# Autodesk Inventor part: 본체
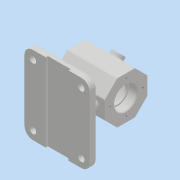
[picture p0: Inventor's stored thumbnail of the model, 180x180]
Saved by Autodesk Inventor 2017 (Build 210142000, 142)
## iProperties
Part Number: 본체
Material: 일반
Document SubType Name: Modeling
Designer: MRC
Density: 1 g/cm^3
Appearance: 기본값
Author: MRC
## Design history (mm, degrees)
sketch "스케치1"
  geometry: L1 (-35, 40)-(35, 40); L2 (35, 40)-(35, 16); L3 (35, 16)-(23, 16); L4 (23, 16)-(23, 14); L5 (23, 14)-(20, 14); L6 (20, 14)-(20, 25); L7 (20, 25)-(-20, 25); L8 (-20, 25)-(-20, 14); L9 (-20, 14)-(-23, 14); L10 (-23, 14)-(-23, 16); L11 (-23, 16)-(-35, 16); L12 (-35, 16)-(-35, 40); L13 (-35, 0)-(35, 0); 3 further points
  constraints: 26 end point, 10 perpendicular, 5 point on line, 3 midpoint, 2 vertical alignment, 1 horizontal
  dimensions: "d0" = 35 distance from line of point (0, 0) L12; "d1" = 35 distance from line of point (0, 0) L2; "d2" = 12 distance of L10.end L11.end; "d4" = 40 distance of L6.end L7.end; "d5" = 12 distance of L2.end L3.end; "d6" = 32 diameter of L11 L13; "d7" = 28 diameter of L9 L13; "d8" = 80 diameter of L1 L13; "d9" = 50 diameter of L7 L13
revolve "회전1" sketch "스케치1" stored, may be unused: angle "d10" = 90 deg
sketch "스케치2"
  geometry: L1 (30, 12.426)-(30, -12.426); L2 (30, -12.426)-(12.426, -30); L3 (12.426, -30)-(-12.426, -30); L4 (-12.426, -30)-(-30, -12.426); L5 (-30, -12.426)-(-30, 12.426); L6 (-30, 12.426)-(-12.426, 30); L7 (-12.426, 30)-(12.426, 30); L8 (12.426, 30)-(30, 12.426); 2 further points
  constraints: 16 end point, 1 coincident, 1 horizontal, 17 other
  dimensions: "d62" = 60 distance between parallel lines of L3 L7
extrude "돌출1" sketch "스케치2" stored distance "d12" = 0; taper "d13" = 0 deg
sketch "스케치4"
  geometry: L1 (-52, -55)-(-62, -55); L2 (-62, -55)-(-62, 55); L3 (-62, 55)-(-52, 55); L4 (-52, 55)-(-52, -55); 2 further points
  constraints: 8 end point, 2 parallel, 1 horizontal, 1 horizontal alignment, 1 midpoint, 1 perpendicular
  dimensions: "d26" = 62 distance from line of point (0, 0) L2; "d27" = 10 distance of L2.end L3.end; "d28" = 110 distance of L1.end L2.end
extrude "돌출2" join sketch "스케치4" stored distance "d29" = 92; taper "d30" = 0 deg
sketch "스케치5"
  geometry: L1 (26, 55)-(66, 55); L2 (26, 61)-(66, 61); L3 (66, 49)-(26, 49); A1 r 6 centre (26, 55) between (26, 61) and (26, 49); A2 r 6 centre (66, 55) between (66, 49) and (66, 61); 2 further points
  constraints: 8 end point, 4 point on circle, 4 tangent, 2 centre point, 1 coincident, 1 horizontal, 1 midpoint, 1 parallel
  dimensions: "d32" = 12 distance between parallel lines of L3 L2; "d97" = 40 distance of L1.start L1.end
extrude "돌출3" join sketch "스케치5" stored distance "d33" = 92; taper "d34" = 0 deg
fillet "모깎기1" dims "d35" = 12
sketch "스케치6"
  geometry: L1 (80, -98)-(80, -12) reference; L2 (68, -110)-(0, -110) reference; L3 (-12, -12)-(-12, -98) reference; L4 (68, 0)-(0, 0) reference; A1 r 12 centre (68, -12) between (80, -12) and (68, 0) reference; A2 r 12 centre (68, -98) between (68, -110) and (80, -98) reference; A3 r 12 centre (0, -98) between (-12, -98) and (0, -110) reference; A4 r 12 centre (0, -12) between (0, 0) and (-12, -12) reference; 5 further points
  constraints: 4 coincident
hole "구멍2" sketch "스케치6" at (0, -12), (68, -12), (68, -98), (0, -98) diameter "d36" = 9; stored, may be unused: countersink angle "d40" = 90 deg, drill point angle "d42" = 118 deg; dims "d37" = 8, "d38" = 4, "d39" = 2, "d41" = 10
sketch "스케치7"
  geometry: L1 (68, -10)-(0, -10) reference; L2 (18, -7)-(50, -7); L3 (50, -7)-(50, -10); L4 (50, -10)-(18, -10); L5 (18, -10)-(18, -7); L6 (18, -7)-(50, -10); L7 (50, -7)-(18, -10); 3 further points
  constraints: 12 end point, 3 midpoint, 2 parallel, 1 horizontal, 1 perpendicular, 1 point on line, 1 vertical alignment
  dimensions: "d43" = 32 distance of L2.start L2.end; "d44" = 3 distance of L2.end L3.end
extrude "돌출4" cut sketch "스케치7" stored distance "d45" = 92; taper "d46" = 0 deg
sketch "스케치11"
  geometry: 2 further points
  constraints: 1 vertical alignment
  dimensions: "d63" = 23 distance of point (30, 12.426) point (30, 35.426)
hole "구멍4" sketch "스케치11" at (30, 35.426) diameter "d64" = 3.242; stored, may be unused: countersink angle "d68" = 90 deg, drill point angle "d70" = 118 deg; dims "d65" = 8, "d66" = 4, "d67" = 2, "d69" = 10
sketch "스케치12"
  geometry: C1 r 8 at (35, -12.426); 1 further point
  constraints: 1 centre point, 1 coincident
  dimensions: "d74" = 16 diameter of C1
extrude "돌출6" join sketch "스케치12" distance "d75" = 5; taper "d76" = 0 deg
hole "구멍5" diameter "d79" = 8; stored, may be unused: countersink angle "d83" = 90 deg, drill point angle "d85" = 118 deg; dims "d77" = 10, "d78" = 10, "d80" = 8, "d81" = 4, "d82" = 2, "d84" = 18
sketch "스케치13"
  geometry: L1 (0, 42.426)-(0, 24.853) reference; L2 (0, 42.426)-(70, 42.426) reference; 2 further points
  constraints: 1 other
  dimensions: "d86" = 35 distance from line of L1 point (35, 12.426); "d87" = 30 distance from line of L2 point (35, 12.426)
feature "엠보싱1" sketch "스케치13" dims "d0" = 35, "d1" = 35, "d2" = 12, "d4" = 40, "d5" = 12, "d6" = 32, "d7" = 28, "d8" = 80, "d9" = 50, "d88" = 0.5, "d89" = 0
fillet "모깎기2" dims "d90" = 3
fillet "모깎기3" dims "d91" = 3
fillet "모깎기4" dims "d92" = 0.3
chamfer "모따기1" distance "d93" = 1; stored, may be unused: second distance "d94" = 2, angle "d95" = 45 deg
fillet "모깎기5" dims "d96" = 1
node "솔리드1"
pattern_circular "원형 패턴2" dims angle "d72" = 360 deg
mirror "미러2"
node "투영된 루프1"
